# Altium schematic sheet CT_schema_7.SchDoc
size 277 x 170 mm
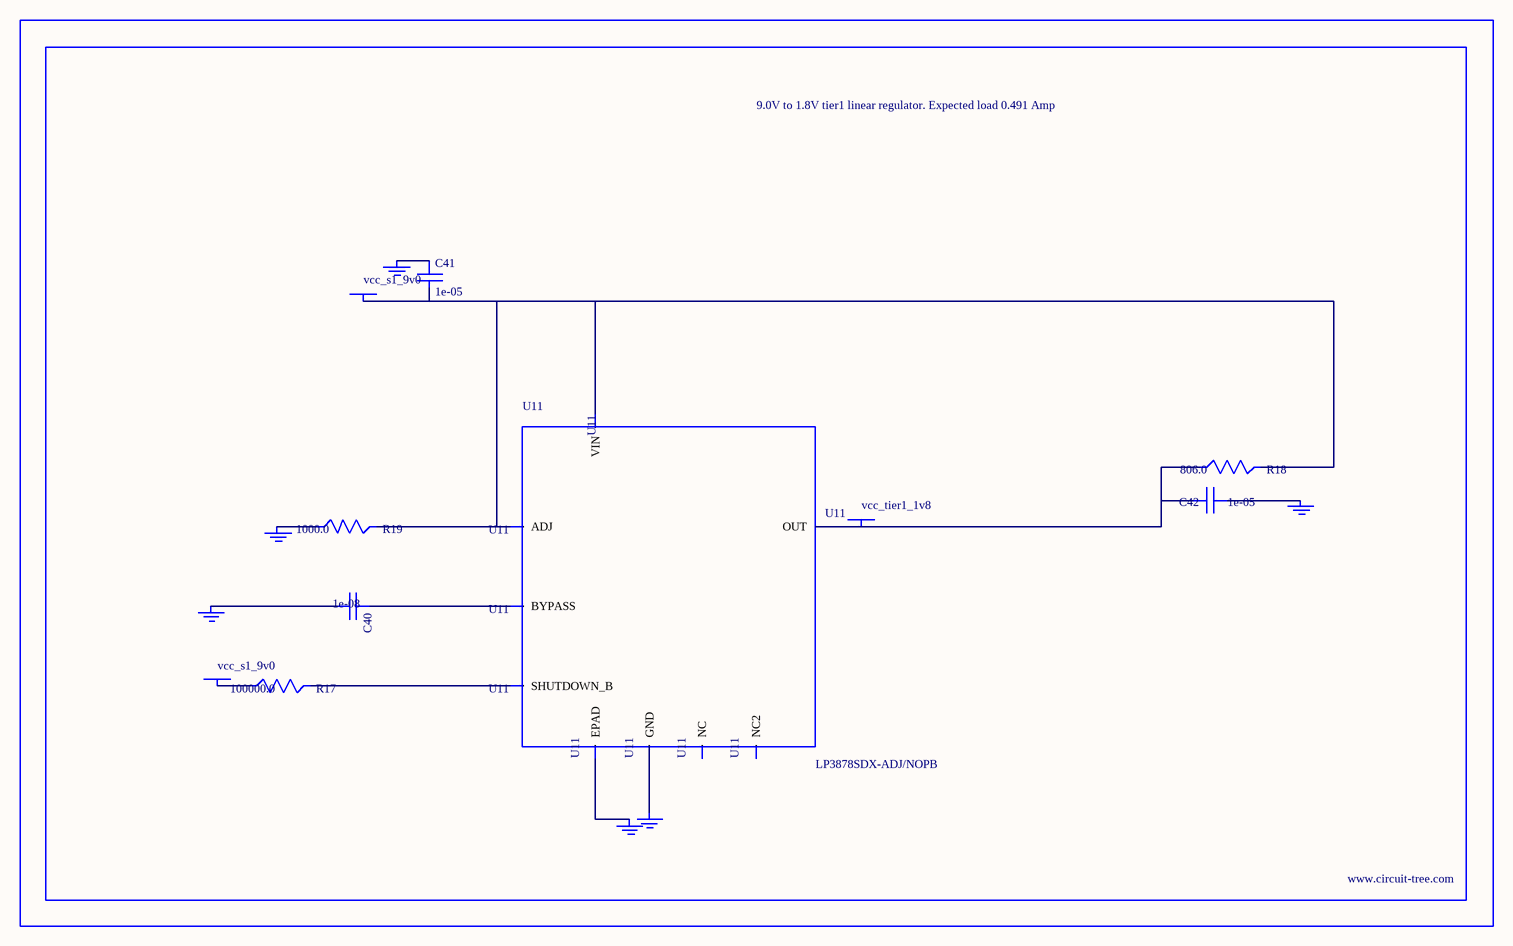
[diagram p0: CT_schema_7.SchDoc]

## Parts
BORDER6  (no value)
C40  1e-08  [C0402]
C41  1e-05  [C1206]
C42  1e-05  [C0805]
GND_INSTANCE_6_0  (no value)
GND_INSTANCE_6_1  (no value)
GND_INSTANCE_6_2  (no value)
GND_INSTANCE_6_3  (no value)
GND_INSTANCE_6_4  (no value)
GND_INSTANCE_6_5  (no value)
POWER_INSTANCE_6_0  vcc_s1_9v0
POWER_INSTANCE_6_1  vcc_s1_9v0
POWER_INSTANCE_6_2  vcc_tier1_1v8
R17  100000.0  [R0603]
R18  806.0  [R0603]
R19  1000.0  [R0603]
U11  LP3878SDX-ADJ/NOPB  [WSON-8]

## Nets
NetC40_1: C40.1 U11.1(BYPASS)
NetC40_2: C40.2 GND_INSTANCE_6_0.0(GND)
NetC41_1: C41.1 GND_INSTANCE_6_1.0(GND)
NetC41_2: C41.2 POWER_INSTANCE_6_0.0(PWR) R18.2 R19.2 U11.4(VIN) U11.6(ADJ)
NetC42_1: C42.1 GND_INSTANCE_6_2.0(GND)
NetC42_2: C42.2 POWER_INSTANCE_6_2.0(PWR) R18.1 U11.5(OUT)
NetGND_INSTANCE_6_3_0: GND_INSTANCE_6_3.0(GND) R19.1
NetGND_INSTANCE_6_4_0: GND_INSTANCE_6_4.0(GND) U11.PAD(EPAD)
NetGND_INSTANCE_6_5_0: GND_INSTANCE_6_5.0(GND) U11.3(GND)
NetPOWER_INSTANCE_6_1_0: POWER_INSTANCE_6_1.0(PWR) R17.1
NetR17_2: R17.2 U11.8(SHUTDOWN_B)

Not connected (* = marked no-connect by the designer): U11 2(NC) 7(NC2)

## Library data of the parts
BORDER6 = BORDER_PAGE6
C40 = C0402C103K3RAC
C41 = C1206C106K3RACTU
C42 = GRM219R60J106ME19D
GND_INSTANCE_6_0-GND_INSTANCE_6_5 = GND
POWER_INSTANCE_6_0-POWER_INSTANCE_6_2 = PWR
R17 = RC0603JR-07100KL
R18 = ERJ-3EKF8060V
R19 = RC0603JR-071KL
